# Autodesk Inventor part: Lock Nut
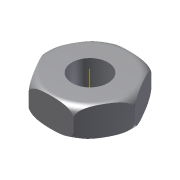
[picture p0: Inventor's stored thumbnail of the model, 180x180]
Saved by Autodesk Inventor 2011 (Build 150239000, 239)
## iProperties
Created: 2009-04
Part Number: Lock Nut
Document SubType Name: Modeling
Designer: Sham
Density: 1 g/cm^3
Mass: 4.64221 g
Surface Area: 21.2945 cm^2
Volume: 4.64221 cm^3
Author: Sham
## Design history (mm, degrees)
sketch "Sketch1"
  geometry: L1 (7.5, 12.99)-(15, 0); L2 (15, 0)-(7.5, -12.99); L3 (7.5, -12.99)-(-7.5, -12.99); L4 (-7.5, -12.99)-(-15, 0); L5 (-15, 0)-(-7.5, 12.99); L6 (-7.5, 12.99)-(7.5, 12.99); C1 r 6 at (0, 0); 1 further point
  constraints: 12 end point, 1 centre point, 1 coincident, 13 other
  dimensions: "d0" = 30 distance of L1.end L4.end; "d1" = 12 diameter of C1
extrude "Extrusion1" new body sketch "Sketch1" distance "d2" = 10; taper "d3" = 0 deg
sketch "Sketch2"
  geometry: L1 (-12, 0)-(-12, -0.022); L2 (-15, 7)-(-15, 3); L3 (0, -2.87)-(0, 12.87) reference; A1 r 3 centre (-12, 7) between (-12, 10) and (-15, 7); A2 r 3 centre (-12, 3) between (-15, 3) and (-12, 0)
  constraints: 4 end point, 4 point on circle, 2 centre point, 1 tangent
revolve "Revolution1" sketch "Sketch2" stored, may be unused: angle "d7" = 90 deg
body "Solid1"
other parameters: "d6" = 90 deg
